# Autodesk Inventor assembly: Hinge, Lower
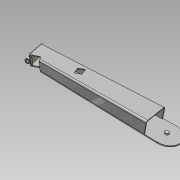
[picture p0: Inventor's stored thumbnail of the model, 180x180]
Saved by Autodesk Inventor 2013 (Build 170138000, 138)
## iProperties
Shininess: 64.0
Length Units: 11269
Angle Units: 11279
Time Units: 11290
Mass Units: 11283
Length Display Precision: 3
Angle Display Precision: 2
Compacted: True
Created: 2005-02
Part Number: Hinge, Lower
Document SubType Name: Assembly
Designer: =<Author>
Manufacturer: Standard
Standards Organization: Custom
Description: =<Part Number>
Density: 0.0
Volumn: 0.0
Area: 0.0
PropertySet Name: Model Information
Control State: 0
Master: False
Checked Out: False
Author: PVitaliy
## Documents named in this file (6)
- Y:\Dropbox\Launch 2013\Eco Material Advisor\Assy, Door\_Data\Assy, Cab\Hinge, Lower.iam
- Y:\Dropbox\Launch 2013\Eco Material Advisor\Assy, Door\_Data\Assy, Cab\glass sheet.ipt
- Y:\Dropbox\Launch 2013\Eco Material Advisor\Assy, Door\_Data\Assy, Cab\Glass section.ipt
- Y:\Dropbox\Launch 2013\Eco Material Advisor\Assy, Door\_Data\Assy, Cab\glass holder.ipt
- Y:\Dropbox\Launch 2013\Eco Material Advisor\Assy, Door\_Data\Assy, Cab\Hinge 1.ipt
- Y:\Dropbox\Launch 2013\Eco Material Advisor\Assy, Door\_Data\Assy, Cab\PK46.51.13.004.ipt
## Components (6 placed, 5 different names)
1. PK46.51.13.004:1 — Insert:2
2. PK46.51.13.004:2 — Insert:1
3. Glass section:1 — Mate:1, Flush:1, Flush:2, Mate:2, Mate:3
4. glass sheet:1 — Mate:1, Flush:1, Flush:2, Flush:3, Mate:4, Insert:1, Insert:2
5. glass holder:1 — Mate:2, Flush:3, Mate:3, Tangent:1, Flush:4
6. Hinge 1:1 — Tangent:1, Mate:4, Flush:4
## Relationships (11: Mate 4, Flush 4, Insert 2, Tangent 1)
- Mate:1: Glass section:1 ↔ glass sheet:1
- Flush:1: Glass section:1 ↔ glass sheet:1
- Flush:2: Glass section:1 ↔ glass sheet:1
- Mate:2: Glass section:1 ↔ glass holder:1
- Flush:3: glass sheet:1 ↔ glass holder:1
- Mate:3: Glass section:1 ↔ glass holder:1
- Tangent:1: glass holder:1 ↔ Hinge 1:1
- Mate:4: glass sheet:1 ↔ Hinge 1:1
- Flush:4: glass holder:1 ↔ Hinge 1:1
- Insert:1: PK46.51.13.004:2 ↔ glass sheet:1
- Insert:2: PK46.51.13.004:1 ↔ glass sheet:1
